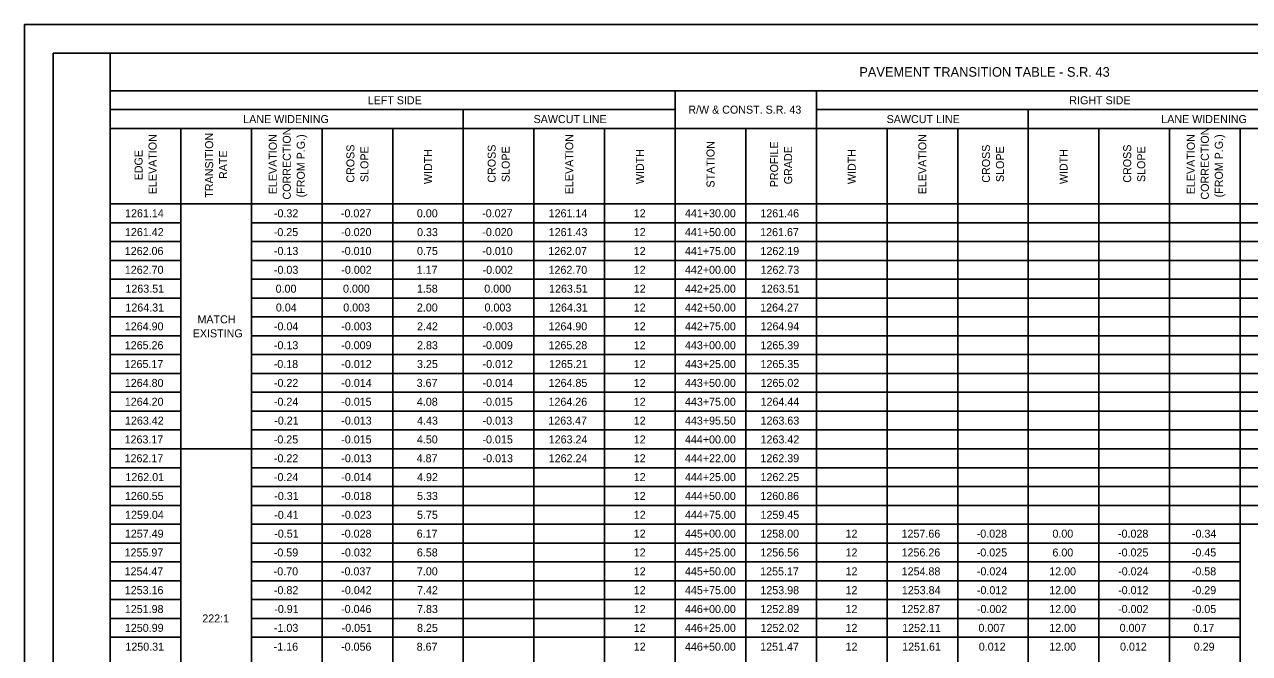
# Model space of a CAD drawing. Extents: x 0 to 34, y 0 to 22.
# Drawn here: x 0 to 21.43, y 11.01 to 22 of the extents above; entities that cross this region are included whole.
import ezdxf

# ---------------------------------------------------------------- set-up
doc = ezdxf.new("R2010")
doc.units = 0
for name, color, linetype in [('SH_Border', 7, 'Continuous'), ('SH_Cut_Line', 7, 'Continuous'), ('SH_Text', 7, 'Continuous')]:
    doc.layers.add(name, color=color, linetype=linetype)

msp = doc.modelspace()

# ---------------------------------------------------------------- linework, layer by layer
at = {"layer": 'SH_Border'}
for points in [[(0.5, 21.5), (1.5, 21.5), (1.5, 0.5), (0.5, 0.5)], [(1.5, 21.5), (33.5, 21.5), (33.5, 0.5), (1.5, 0.5)]]:
    msp.add_lwpolyline(points, close=True, dxfattribs=at)
at = {"layer": 'SH_Cut_Line'}
msp.add_lwpolyline([(0, 0), (34, 0), (34, 22), (0, 22)], close=True, dxfattribs=at)
at = {"layer": 'SH_Text'}
for p, q in [((1.5, 21.5), (32.004, 21.5)), ((1.5, 21.5), (1.5, 3.053)), ((1.5, 20.841), (32.004, 20.841)), ((11.382, 20.841), (11.382, 3.053)), ((13.853, 20.841), (13.853, 3.053)), ((1.5, 20.512), (11.382, 20.512)), ((7.676, 20.512), (7.676, 3.053)), ((13.853, 20.512), (23.735, 20.512)), ((17.559, 20.512), (17.559, 3.053)), ((1.5, 20.182), (23.735, 20.182)), ((2.735, 20.182), (2.735, 3.053)), ((3.971, 20.182), (3.971, 3.053)), ((5.206, 20.182), (5.206, 3.053)), ((6.441, 20.182), (6.441, 3.053)), ((8.912, 20.182), (8.912, 3.053)), ((10.147, 20.182), (10.147, 3.053)), ((12.618, 20.182), (12.618, 3.053)), ((15.088, 20.182), (15.088, 3.053)), ((16.324, 20.182), (16.324, 3.053)), ((18.794, 20.182), (18.794, 3.053)), ((20.029, 20.182), (20.029, 3.053)), ((21.265, 20.182), (21.265, 3.053)), ((1.5, 18.865), (32.004, 18.865)), ((1.5, 18.535), (2.735, 18.535)), ((3.971, 18.535), (32.004, 18.535)), ((1.5, 18.206), (2.735, 18.206)), ((3.971, 18.206), (32.004, 18.206)), ((1.5, 17.876), (2.735, 17.876)), ((3.971, 17.876), (32.004, 17.876)), ((1.5, 17.547), (2.735, 17.547)), ((3.971, 17.547), (32.004, 17.547)), ((1.5, 17.218), (2.735, 17.218)), ((3.971, 17.218), (32.004, 17.218)), ((1.5, 16.888), (2.735, 16.888)), ((3.971, 16.888), (32.004, 16.888)), ((1.5, 16.559), (2.735, 16.559)), ((3.971, 16.559), (32.004, 16.559)), ((1.5, 16.229), (2.735, 16.229)), ((3.971, 16.229), (32.004, 16.229)), ((1.5, 15.9), (2.735, 15.9)), ((3.971, 15.9), (32.004, 15.9)), ((1.5, 15.571), (2.735, 15.571)), ((3.971, 15.571), (32.004, 15.571)), ((1.5, 15.241), (2.735, 15.241)), ((3.971, 15.241), (32.004, 15.241)), ((1.5, 14.912), (2.735, 14.912)), ((3.971, 14.912), (32.004, 14.912)), ((1.5, 14.582), (32.004, 14.582)), ((1.5, 14.253), (2.735, 14.253)), ((3.971, 14.253), (32.004, 14.253)), ((1.5, 13.924), (2.735, 13.924)), ((3.971, 13.924), (32.004, 13.924)), ((1.5, 13.594), (2.735, 13.594)), ((3.971, 13.594), (32.004, 13.594)), ((1.5, 13.265), (2.735, 13.265)), ((3.971, 13.265), (32.004, 13.265)), ((1.5, 12.935), (2.735, 12.935)), ((3.971, 12.935), (21.265, 12.935)), ((1.5, 12.606), (2.735, 12.606)), ((3.971, 12.606), (21.265, 12.606)), ((1.5, 12.276), (2.735, 12.276)), ((3.971, 12.276), (21.265, 12.276)), ((1.5, 11.947), (2.735, 11.947)), ((3.971, 11.947), (21.265, 11.947)), ((1.5, 11.618), (2.735, 11.618)), ((3.971, 11.618), (21.265, 11.618)), ((1.5, 11.288), (2.735, 11.288)), ((3.971, 11.288), (21.265, 11.288))]:
    msp.add_line(p, q, dxfattribs=at)

# ---------------------------------------------------------------- texts
for s, height, p in [('PAVEMENT TRANSITION TABLE - S.R. 43', 0.168, (14.602, 21.087)), ('LEFT SIDE', 0.14, (6.003, 20.606)), ('R/W & CONST. S.R. 43', 0.14, (11.612, 20.442)), ('RIGHT SIDE', 0.14, (18.276, 20.606)), ('LANE WIDENING', 0.14, (3.826, 20.277)), ('SAWCUT LINE', 0.14, (8.905, 20.277)), ('SAWCUT LINE', 0.14, (15.081, 20.277)), ('LANE WIDENING', 0.14, (19.885, 20.277)), ('1261.14', 0.14, (1.759, 18.63)), ('-0.32', 0.14, (4.363, 18.63)), ('-0.027', 0.14, (5.535, 18.63)), ('0.00', 0.14, (6.864, 18.63)), ('-0.027', 0.14, (8.006, 18.63)), ('1261.14', 0.14, (9.169, 18.63)), ('12', 0.14, (10.657, 18.63)), (' 441+30.00', 0.14, (11.501, 18.63)), ('1261.46', 0.14, (12.872, 18.63)), ('1261.42', 0.14, (1.758, 18.301)), ('-0.25', 0.14, (4.361, 18.301)), ('-0.020', 0.14, (5.539, 18.301)), ('0.33', 0.14, (6.867, 18.301)), ('-0.020', 0.14, (8.009, 18.301)), ('1261.43', 0.14, (9.17, 18.301)), ('12', 0.14, (10.657, 18.301)), (' 441+50.00', 0.14, (11.501, 18.301)), ('1261.67', 0.14, (12.869, 18.301)), ('1262.06', 0.14, (1.754, 17.971)), ('-0.13', 0.14, (4.363, 17.971)), ('-0.010', 0.14, (5.539, 17.971)), ('0.75', 0.14, (6.866, 17.971)), ('-0.010', 0.14, (8.009, 17.971)), ('1262.07', 0.14, (9.163, 17.971)), ('12', 0.14, (10.657, 17.971)), (' 441+75.00', 0.14, (11.501, 17.971)), ('1262.19', 0.14, (12.874, 17.971)), ('1262.70', 0.14, (1.755, 17.642)), ('-0.03', 0.14, (4.363, 17.642)), ('-0.002', 0.14, (5.542, 17.642)), ('1.17', 0.14, (6.86, 17.642)), ('-0.002', 0.14, (8.013, 17.642)), ('1262.70', 0.14, (9.167, 17.642)), ('12', 0.14, (10.657, 17.642)), (' 442+00.00', 0.14, (11.501, 17.642)), ('1262.73', 0.14, (12.876, 17.642)), ('1263.51', 0.14, (1.765, 17.312)), ('0.00', 0.14, (4.393, 17.312)), ('0.000', 0.14, (5.572, 17.312)), ('1.58', 0.14, (6.864, 17.312)), ('0.000', 0.14, (8.043, 17.312)), ('1263.51', 0.14, (9.176, 17.312)), ('12', 0.14, (10.657, 17.312)), (' 442+25.00', 0.14, (11.501, 17.312)), ('1263.51', 0.14, (12.882, 17.312)), ('1264.31', 0.14, (1.765, 16.983)), ('0.04', 0.14, (4.397, 16.983)), ('0.003', 0.14, (5.576, 16.983)), ('2.00', 0.14, (6.864, 16.983)), ('0.003', 0.14, (8.047, 16.983)), ('1264.31', 0.14, (9.176, 16.983)), ('12', 0.14, (10.657, 16.983)), (' 442+50.00', 0.14, (11.501, 16.983)), ('1264.27', 0.14, (12.869, 16.983)), ('1264.90', 0.14, (1.755, 16.654)), ('MATCH ', 0.14, (3.026, 16.776)), ('-0.04', 0.14, (4.363, 16.654)), ('-0.003', 0.14, (5.542, 16.654)), ('2.42', 0.14, (6.867, 16.654)), ('-0.003', 0.14, (8.013, 16.654)), ('1264.90', 0.14, (9.167, 16.654)), ('12', 0.14, (10.657, 16.654)), (' 442+75.00', 0.14, (11.501, 16.654)), ('1264.94', 0.14, (12.876, 16.654)), ('EXISTING', 0.14, (2.943, 16.531)), ('1265.26', 0.14, (1.754, 16.324)), ('-0.13', 0.14, (4.363, 16.324)), ('-0.009', 0.14, (5.54, 16.324)), ('2.83', 0.14, (6.867, 16.324)), ('-0.009', 0.14, (8.011, 16.324)), ('1265.28', 0.14, (9.167, 16.324)), ('12', 0.14, (10.657, 16.324)), (' 443+00.00', 0.14, (11.501, 16.324)), ('1265.39', 0.14, (12.874, 16.324)), ('1265.17', 0.14, (1.751, 15.995)), ('-0.18', 0.14, (4.36, 15.995)), ('-0.012', 0.14, (5.542, 15.995)), ('3.25', 0.14, (6.866, 15.995)), ('-0.012', 0.14, (8.013, 15.995)), ('1265.21', 0.14, (9.176, 15.995)), ('12', 0.14, (10.657, 15.995)), (' 443+25.00', 0.14, (11.501, 15.995)), ('1265.35', 0.14, (12.875, 15.995)), ('1264.80', 0.14, (1.755, 15.665)), ('-0.22', 0.14, (4.363, 15.665)), ('-0.014', 0.14, (5.542, 15.665)), ('3.67', 0.14, (6.86, 15.665)), ('-0.014', 0.14, (8.013, 15.665)), ('1264.85', 0.14, (9.169, 15.665)), ('12', 0.14, (10.657, 15.665)), (' 443+50.00', 0.14, (11.501, 15.665)), ('1265.02', 0.14, (12.876, 15.665)), ('1264.20', 0.14, (1.755, 15.336)), ('-0.24', 0.14, (4.363, 15.336)), ('-0.015', 0.14, (5.541, 15.336)), ('4.08', 0.14, (6.864, 15.336)), ('-0.015', 0.14, (8.011, 15.336)), ('1264.26', 0.14, (9.166, 15.336)), ('12', 0.14, (10.657, 15.336)), (' 443+75.00', 0.14, (11.501, 15.336)), ('1264.44', 0.14, (12.876, 15.336)), ('1263.42', 0.14, (1.758, 15.006)), ('-0.21', 0.14, (4.369, 15.006)), ('-0.013', 0.14, (5.542, 15.006)), ('4.43', 0.14, (6.867, 15.006)), ('-0.013', 0.14, (8.013, 15.006)), ('1263.47', 0.14, (9.163, 15.006)), ('12', 0.14, (10.657, 15.006)), (' 443+95.50', 0.14, (11.501, 15.006)), ('1263.63', 0.14, (12.876, 15.006)), ('1263.17', 0.14, (1.751, 14.677)), ('-0.25', 0.14, (4.361, 14.677)), ('-0.015', 0.14, (5.541, 14.677)), ('4.50', 0.14, (6.864, 14.677)), ('-0.015', 0.14, (8.011, 14.677)), ('1263.24', 0.14, (9.17, 14.677)), ('12', 0.14, (10.657, 14.677)), (' 444+00.00', 0.14, (11.501, 14.677)), ('1263.42', 0.14, (12.876, 14.677)), ('1262.17', 0.14, (1.751, 14.348)), ('-0.22', 0.14, (4.363, 14.348)), ('-0.013', 0.14, (5.542, 14.348)), ('4.87', 0.14, (6.86, 14.348)), ('-0.013', 0.14, (8.013, 14.348)), ('1262.24', 0.14, (9.17, 14.348)), ('12', 0.14, (10.657, 14.348)), (' 444+22.00', 0.14, (11.501, 14.348)), ('1262.39', 0.14, (12.874, 14.348)), ('1262.01', 0.14, (1.765, 14.018)), ('-0.24', 0.14, (4.363, 14.018)), ('-0.014', 0.14, (5.542, 14.018)), ('4.92', 0.14, (6.867, 14.018)), ('12', 0.14, (10.657, 14.018)), (' 444+25.00', 0.14, (11.501, 14.018)), ('1262.25', 0.14, (12.875, 14.018)), ('1260.55', 0.14, (1.757, 13.689)), ('-0.31', 0.14, (4.369, 13.689)), ('-0.018', 0.14, (5.539, 13.689)), ('5.33', 0.14, (6.867, 13.689)), ('12', 0.14, (10.657, 13.689)), (' 444+50.00', 0.14, (11.501, 13.689)), ('1260.86', 0.14, (12.872, 13.689)), ('1259.04', 0.14, (1.759, 13.359)), ('-0.41', 0.14, (4.369, 13.359)), ('-0.023', 0.14, (5.542, 13.359)), ('12', 0.14, (10.657, 13.359)), (' 444+75.00', 0.14, (11.501, 13.359)), ('1259.45', 0.14, (12.875, 13.359)), ('5.75', 0.14, (6.866, 13.359)), ('1257.49', 0.14, (1.756, 13.03)), ('-0.51', 0.14, (4.369, 13.03)), ('-0.028', 0.14, (5.539, 13.03)), ('6.17', 0.14, (6.86, 13.03)), ('12', 0.14, (10.657, 13.03)), (' 445+00.00', 0.14, (11.501, 13.03)), ('1258.00', 0.14, (12.872, 13.03)), ('12', 0.14, (14.362, 13.03)), ('1257.66', 0.14, (15.342, 13.03)), ('-0.028', 0.14, (16.657, 13.03)), ('0.00', 0.14, (17.981, 13.03)), ('-0.028', 0.14, (19.128, 13.03)), ('-0.34', 0.14, (20.422, 13.03)), ('1255.97', 0.14, (1.751, 12.701)), ('-0.59', 0.14, (4.361, 12.701)), ('-0.032', 0.14, (5.542, 12.701)), ('6.58', 0.14, (6.864, 12.701)), ('12', 0.14, (10.657, 12.701)), (' 445+25.00', 0.14, (11.501, 12.701)), ('1256.56', 0.14, (12.872, 12.701)), ('12', 0.14, (14.362, 12.701)), ('1256.26', 0.14, (15.342, 12.701)), ('-0.025', 0.14, (16.658, 12.701)), ('6.00', 0.14, (17.981, 12.701)), ('-0.025', 0.14, (19.129, 12.701)), ('-0.45', 0.14, (20.42, 12.701)), ('1254.47', 0.14, (1.751, 12.371)), ('-0.70', 0.14, (4.359, 12.371)), ('-0.037', 0.14, (5.535, 12.371)), ('7.00', 0.14, (6.864, 12.371)), ('12', 0.14, (10.657, 12.371)), (' 445+50.00', 0.14, (11.501, 12.371)), ('1255.17', 0.14, (12.869, 12.371)), ('12', 0.14, (14.362, 12.371)), ('1254.88', 0.14, (15.344, 12.371)), ('-0.024', 0.14, (16.66, 12.371)), ('12.00', 0.14, (17.925, 12.371)), ('-0.024', 0.14, (19.131, 12.371)), ('-0.58', 0.14, (20.419, 12.371)), ('1253.16', 0.14, (1.754, 12.042)), ('-0.82', 0.14, (4.363, 12.042)), ('-0.042', 0.14, (5.542, 12.042)), ('7.42', 0.14, (6.867, 12.042)), ('12', 0.14, (10.657, 12.042)), (' 445+75.00', 0.14, (11.501, 12.042)), ('1253.98', 0.14, (12.873, 12.042)), ('12', 0.14, (14.362, 12.042)), ('1253.84', 0.14, (15.347, 12.042)), ('-0.012', 0.14, (16.66, 12.042)), ('12.00', 0.14, (17.925, 12.042)), ('-0.012', 0.14, (19.13, 12.042)), ('-0.29', 0.14, (20.419, 12.042)), ('1251.98', 0.14, (1.755, 11.712)), ('-0.91', 0.14, (4.369, 11.712)), ('-0.046', 0.14, (5.538, 11.712)), ('7.83', 0.14, (6.867, 11.712)), ('12', 0.14, (10.657, 11.712)), (' 446+00.00', 0.14, (11.501, 11.712)), ('1252.89', 0.14, (12.874, 11.712)), ('12', 0.14, (14.362, 11.712)), ('1252.87', 0.14, (15.34, 11.712)), ('-0.002', 0.14, (16.66, 11.712)), ('12.00', 0.14, (17.925, 11.712)), ('-0.002', 0.14, (19.13, 11.712)), ('-0.05', 0.14, (20.42, 11.712)), ('222:1', 0.14, (3.11, 11.548)), ('1250.99', 0.14, (1.756, 11.383)), ('-1.03', 0.14, (4.363, 11.383)), ('-0.051', 0.14, (5.548, 11.383)), ('8.25', 0.14, (6.866, 11.383)), ('12', 0.14, (10.657, 11.383)), (' 446+25.00', 0.14, (11.501, 11.383)), ('1252.02', 0.14, (12.876, 11.383)), ('12', 0.14, (14.362, 11.383)), ('1252.11', 0.14, (15.353, 11.383)), ('0.007', 0.14, (16.687, 11.383)), ('12.00', 0.14, (17.925, 11.383)), ('0.007', 0.14, (19.157, 11.383)), ('0.17', 0.14, (20.448, 11.383)), ('1250.31', 0.14, (1.765, 11.054)), ('-1.16', 0.14, (4.359, 11.054)), ('-0.056', 0.14, (5.538, 11.054)), ('8.67', 0.14, (6.86, 11.054)), ('12', 0.14, (10.657, 11.054)), (' 446+50.00', 0.14, (11.501, 11.054)), ('1251.47', 0.14, (12.869, 11.054)), ('12', 0.14, (14.362, 11.054)), ('1251.61', 0.14, (15.353, 11.054)), ('0.012', 0.14, (16.693, 11.054)), ('12.00', 0.14, (17.925, 11.054)), ('0.012', 0.14, (19.164, 11.054)), ('0.29', 0.14, (20.453, 11.054))]:
    msp.add_text(s, height=height, dxfattribs=at).set_placement(p)
for s, p in [('CORRECTION', (4.658, 18.94)), ('CORRECTION', (20.717, 18.94)), ('ELEVATION', (2.31, 19.033)), ('TRANSITION', (3.3, 18.973)), ('ELEVATION', (4.413, 19.033)), ('(FROM P.G.)', (4.903, 18.978)), ('ELEVATION', (9.599, 19.033)), ('STATION', (12.07, 19.15)), ('PROFILE', (13.183, 19.155)), ('ELEVATION', (15.776, 19.033)), ('ELEVATION', (20.472, 19.033)), ('(FROM P.G.)', (20.962, 18.978)), ('EDGE', (2.065, 19.276)), ('RATE', (3.545, 19.299)), ('CROSS', (5.771, 19.235)), ('SLOPE', (6.016, 19.246)), ('WIDTH', (7.129, 19.21)), ('CROSS', (8.242, 19.235)), ('SLOPE', (8.487, 19.246)), ('WIDTH', (10.835, 19.21)), ('GRADE', (13.428, 19.207)), ('WIDTH', (14.541, 19.21)), ('CROSS', (16.889, 19.235)), ('SLOPE', (17.134, 19.246)), ('WIDTH', (18.246, 19.21)), ('CROSS', (19.359, 19.235)), ('SLOPE', (19.604, 19.246))]:
    msp.add_text(s, height=0.14, rotation=90, dxfattribs=at).set_placement(p)

doc.saveas('drawing.dxf')
